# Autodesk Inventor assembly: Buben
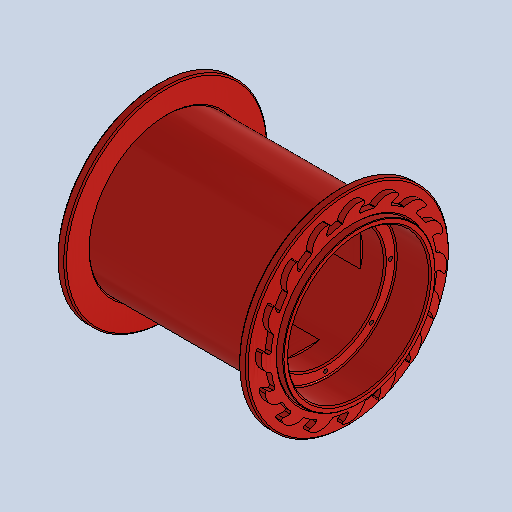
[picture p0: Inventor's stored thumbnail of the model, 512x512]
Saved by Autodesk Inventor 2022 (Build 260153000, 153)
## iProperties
Created: 2025-05
Part Number: Buben
Document SubType Name: Assembly
Designer: jbart
Mass: 71047.9 g
Surface Area: 34761.7 cm^2
Volume: 71047.9 cm^3
Density: 1 g/cm^3
Author: jbart
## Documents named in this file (4)
- C:\Users\jbart\OneDrive\Dokumenty\Inventor\Převodovka navijáku\Buben - nový.iam
- C:\Users\jbart\OneDrive\Dokumenty\Inventor\Převodovka navijáku\Plášť bubnu.ipt
- C:\Users\jbart\OneDrive\Dokumenty\Inventor\Převodovka navijáku\Bočnice - levá.ipt
- C:\Users\jbart\OneDrive\Dokumenty\Inventor\Převodovka navijáku\Bočnice - pravá.ipt
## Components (3 placed, 3 different names)
1. Plášť bubnu:1 — Proti sobě:1, Proti sobě:2, Stejný směr:1, Proti sobě:3, Proti sobě:4, Stejný směr:2
2. Bočnice - levá:1 — Proti sobě:1, Proti sobě:2, Stejný směr:1
3. Bočnice - pravá:1 — Proti sobě:3, Proti sobě:4, Stejný směr:2
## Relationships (6: Mate 4, Flush 2)
- Proti sobě:1 [Mate]: Plášť bubnu:1 ↔ Bočnice - levá:1
- Proti sobě:2 [Mate]: Plášť bubnu:1 ↔ Bočnice - levá:1
- Stejný směr:1 [Flush]: Plášť bubnu:1 ↔ Bočnice - levá:1
- Proti sobě:3 [Mate]: Plášť bubnu:1 ↔ Bočnice - pravá:1
- Proti sobě:4 [Mate]: Plášť bubnu:1 ↔ Bočnice - pravá:1
- Stejný směr:2 [Flush]: Plášť bubnu:1 ↔ Bočnice - pravá:1
